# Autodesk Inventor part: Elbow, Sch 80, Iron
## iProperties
Author: Administrator
Shininess: 56.0
PropertySet Name: _Private Model Information
Created: 2001-01
Part Number: Elbow, Sch 80, Iron
Material: Steel, Mild
Document SubType Name: Modeling
Designer: Administrator
Control State: 0
Master: False
Checked Out: False
PropertySet Name: Design Tracking Control
Density: 7.86
Volumn: 130.4024193941862
Area: 435.5867292916407
PropertySet Name: Model Information
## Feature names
1. Revolution1
2. Extrusion5
3. Extrusion6
4. Extrusion7
5. Extrusion8
6. Revolution2
7. Revolution3
8. Fillet2
